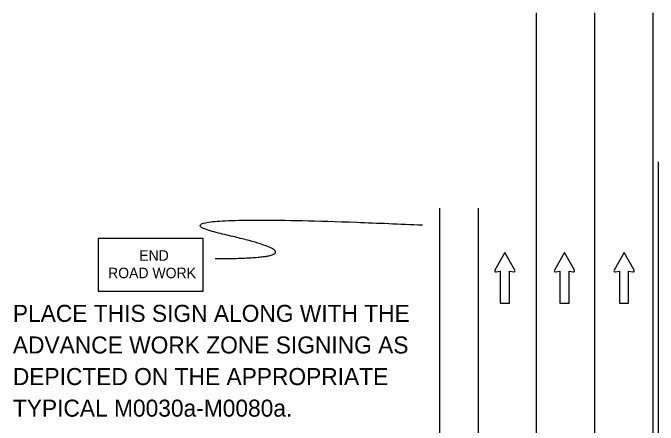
# Model space of a CAD drawing. Extents: x 16473 to 18475, y 7005 to 8296.
# Drawn here: x 16738.6 to 17004.1, y 8126.1 to 8295.7 of the extents above; entities that cross this region are included whole.
import ezdxf

# ---------------------------------------------------------------- set-up
doc = ezdxf.new("R2010")
doc.units = 0
for name, color, linetype in [('ALI_LEGAL_EX', 7, 'Continuous'), ('MT_SCRATCH_LEVEL_E', 7, 'Continuous'), ('PAVT_EDGE_EX', 7, 'Continuous'), ('TRAFFIC_SIGNS_PR', 7, 'Continuous'), ('TYPICAL_TEXT_DIMEN_PR', 7, 'Continuous')]:
    doc.layers.add(name, color=color, linetype=linetype)

msp = doc.modelspace()

# ---------------------------------------------------------------- linework, layer by layer
at = {"layer": 'ALI_LEGAL_EX'}
for p, q in [((16954.13, 7361.76), (16954.13, 8295.71)), ((16978.13, 7361.76), (16978.13, 8295.71)), ((17002.13, 7361.76), (17002.13, 8295.71)), ((17004.11, 8234.45), (17004.11, 7405.27))]:
    msp.add_line(p, q, dxfattribs=at)
for points in [[(16954.13, 8161.76), (16954.13, 8186.76)], [(16978.13, 8161.76), (16978.13, 8186.76)], [(17002.13, 8161.76), (17002.13, 8186.76)]]:
    msp.add_lwpolyline(points, dxfattribs=at)
at = {"layer": 'MT_SCRATCH_LEVEL_E'}
for p, q in [((16941.04, 8197.08), (16936.93, 8189.84)), ((16945.18, 8189.84), (16941.04, 8197.08)), ((16965.57, 8197.08), (16961.46, 8189.84)), ((16969.71, 8189.84), (16965.57, 8197.08)), ((16990.1, 8197.08), (16985.98, 8189.84)), ((16994.24, 8189.84), (16990.1, 8197.08)), ((16937.41, 8189.16), (16939.19, 8189.47)), ((16939.19, 8189.47), (16939.19, 8176.22)), ((16942.93, 8176.22), (16942.93, 8189.47)), ((16942.93, 8189.47), (16944.7, 8189.16)), ((16961.94, 8189.16), (16963.71, 8189.47)), ((16963.71, 8189.47), (16963.71, 8176.22)), ((16967.46, 8176.22), (16967.46, 8189.47)), ((16967.46, 8189.47), (16969.23, 8189.16)), ((16986.47, 8189.16), (16988.24, 8189.47)), ((16988.24, 8189.47), (16988.24, 8176.22)), ((16991.99, 8176.22), (16991.99, 8189.47)), ((16991.99, 8189.47), (16993.76, 8189.16)), ((16939.19, 8176.22), (16942.93, 8176.22)), ((16963.71, 8176.22), (16967.46, 8176.22)), ((16988.24, 8176.22), (16991.99, 8176.22))]:
    msp.add_line(p, q, dxfattribs=at)
for centre, start, end in [((16937.33, 8189.62), 150.4248, 279.9638), ((16944.77, 8189.62), 260.0362, 29.7731), ((16961.86, 8189.62), 150.4248, 279.9638), ((16969.3, 8189.62), 260.0362, 29.7731), ((16986.39, 8189.62), 150.4248, 279.9638), ((16993.83, 8189.62), 260.0362, 29.7731)]:
    msp.add_arc(centre, 0.463, start, end, dxfattribs=at)
at = {"layer": 'PAVT_EDGE_EX'}
for p, q in [((16914.13, 8215.4), (16914.13, 7361.76)), ((16930.13, 8215.4), (16930.13, 7361.76))]:
    msp.add_line(p, q, dxfattribs=at)
at = {"layer": 'TRAFFIC_SIGNS_PR'}
msp.add_lwpolyline([(16773.73, 8181.23), (16816.93, 8181.23), (16816.93, 8202.83), (16773.73, 8202.83)], close=True, dxfattribs=at)
at = {"layer": 'TYPICAL_TEXT_DIMEN_PR'}
msp.add_open_spline([(16821.85, 8194.62), (16869.08, 8194.62), (16784.06, 8213.97), (16907.16, 8208.48)], degree=2, dxfattribs=at)

# ---------------------------------------------------------------- texts
at = {"layer": 'TRAFFIC_SIGNS_PR'}
for s, height, p in [('END', 4.31, (16790.6, 8193.75)), ('ROAD WORK', 4.31, (16777.79, 8186.57)), ('PLACE THIS SIGN ALONG WITH THE', 7, (16738.61, 8168.59)), ('ADVANCE WORK ZONE SIGNING AS', 7, (16738.61, 8155.59)), ('DEPICTED ON THE APPROPRIATE', 7, (16738.61, 8142.59)), ('TYPICAL M0030a-M0080a.', 7, (16738.61, 8129.59))]:
    msp.add_text(s, height=height, dxfattribs=at).set_placement(p)

doc.saveas('drawing.dxf')
